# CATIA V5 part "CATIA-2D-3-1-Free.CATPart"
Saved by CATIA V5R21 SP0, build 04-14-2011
Part number: CATIA-2D-3-1-Free
Bounding box of the stored display mesh (mm): x -14.997 to 120, y 0 to 0, z -45 to 45
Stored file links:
  C:\Users\Rasoul Mohammadi\Desktop\CATIA-Free\2D\CATIA-2D-3-1-Free.CATPart
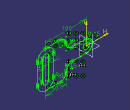
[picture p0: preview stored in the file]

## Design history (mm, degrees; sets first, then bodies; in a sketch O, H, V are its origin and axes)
Body1 (main body)
  Sketch1 on zx-plane, origin (0, 0, 0), H (-1, 0, 0), V (0, 0, 1)
    circle A1 centre (0, 0) radius 7.5
    construction line L1 (-100, 25) -> (-100, -25)
    point P1 (-100, 25)
    point P2 (-100, -25)
    line L2 (-92.5, 25) -> (-92.5, -25)
    line L3 (-107.5, -25) -> (-107.5, 25)
    arc A2 centre (-100, -25) radius 7.5 from (-92.5, -25) to (-107.5, -25) cw
    arc A3 centre (-100, 25) radius 7.5 from (-107.5, 25) to (-92.5, 25) cw
    construction line L4 (-100, 25) -> (-100, -25)
    line L5 (-80, 25) -> (-80, -25)
    line L6 (-120, -25) -> (-120, 25)
    arc A4 centre (-100, -25) radius 20 from (-80, -25) to (-120, -25) cw
    arc A5 centre (-100, 25) radius 20 from (-120, 25) to (-80, 25) cw
    point P11 (-100, 45)
    line L7 (-100, 45) -> (-65, 45)
    point P12 (-50, 45)
    line L8 (-50, 30) -> (-50, 30)
    point P13 (-50, 15)
    line L9 (-35, 15) -> (0, 15)
    point P14 (0, 15)
    point P15 (-50, -45)
    point P16 (-100, -45)
    line L10 (-100, -45) -> (-65, -45)
    point P17 (-50, -15)
    line L11 (-50, -30) -> (-50, -30)
    point P18 (0, -15)
    line L12 (-35, -15) -> (0, -15)
    arc A6 centre (0, 0) radius 15 from (0, -15) to (0, 15) ccw
    arc A7 centre (-65, 30) radius 15 from (-65, 45) to (-50, 30) cw
    arc A8 centre (-35, 30) radius 15 from (-50, 30) to (-35, 15) ccw
    arc A9 centre (-35, -30) radius 15 from (-50, -30) to (-35, -15) cw
    point P25 (-50, -30)
    arc A10 centre (-65, -30) radius 15 from (-65, -45) to (-50, -30) ccw
    radius A1 = 7.5
    distance L1 L2 = 7.5
    length L1 = 50
    distance L4 L5 = 20
    radius A7 = 15
    radius A8 = 15 {= Sketch1.radius(A7)}
    radius A9 = 15 {= Sketch1.radius(A7)}
    radius A10 = 15 {= Sketch1.radius(A7)}
    radius A6 = 15
    distance L4 V = 100
    distance L4 P25 = 50
    vertical: L1 V, L4 V, L8 V
    tangency: A2 L2, A3 L2, A2 L3, A3 L3, A4 L5, A5 L5, A4 L6, A5 L6, L7 A5, A6 L9, A7 L7, A7 L8, A8 L8, A8 L9, A9 L11, A9 L12, A10 L10, A10 L11
    symmetry: P1 P2 H, P12 P15 H, P11 P16 H, L7 L10 H, P13 P17 H, L8 L11 H, P14 P18 H, L9 L12 H
    coincidence: P11 A5, P11 L4, P14 V, L7 P12, L8 P12, L8 P13, L9 P13, L11 P17, L12 P17, L10 P15, L11 P15
    horizontal: L9 H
